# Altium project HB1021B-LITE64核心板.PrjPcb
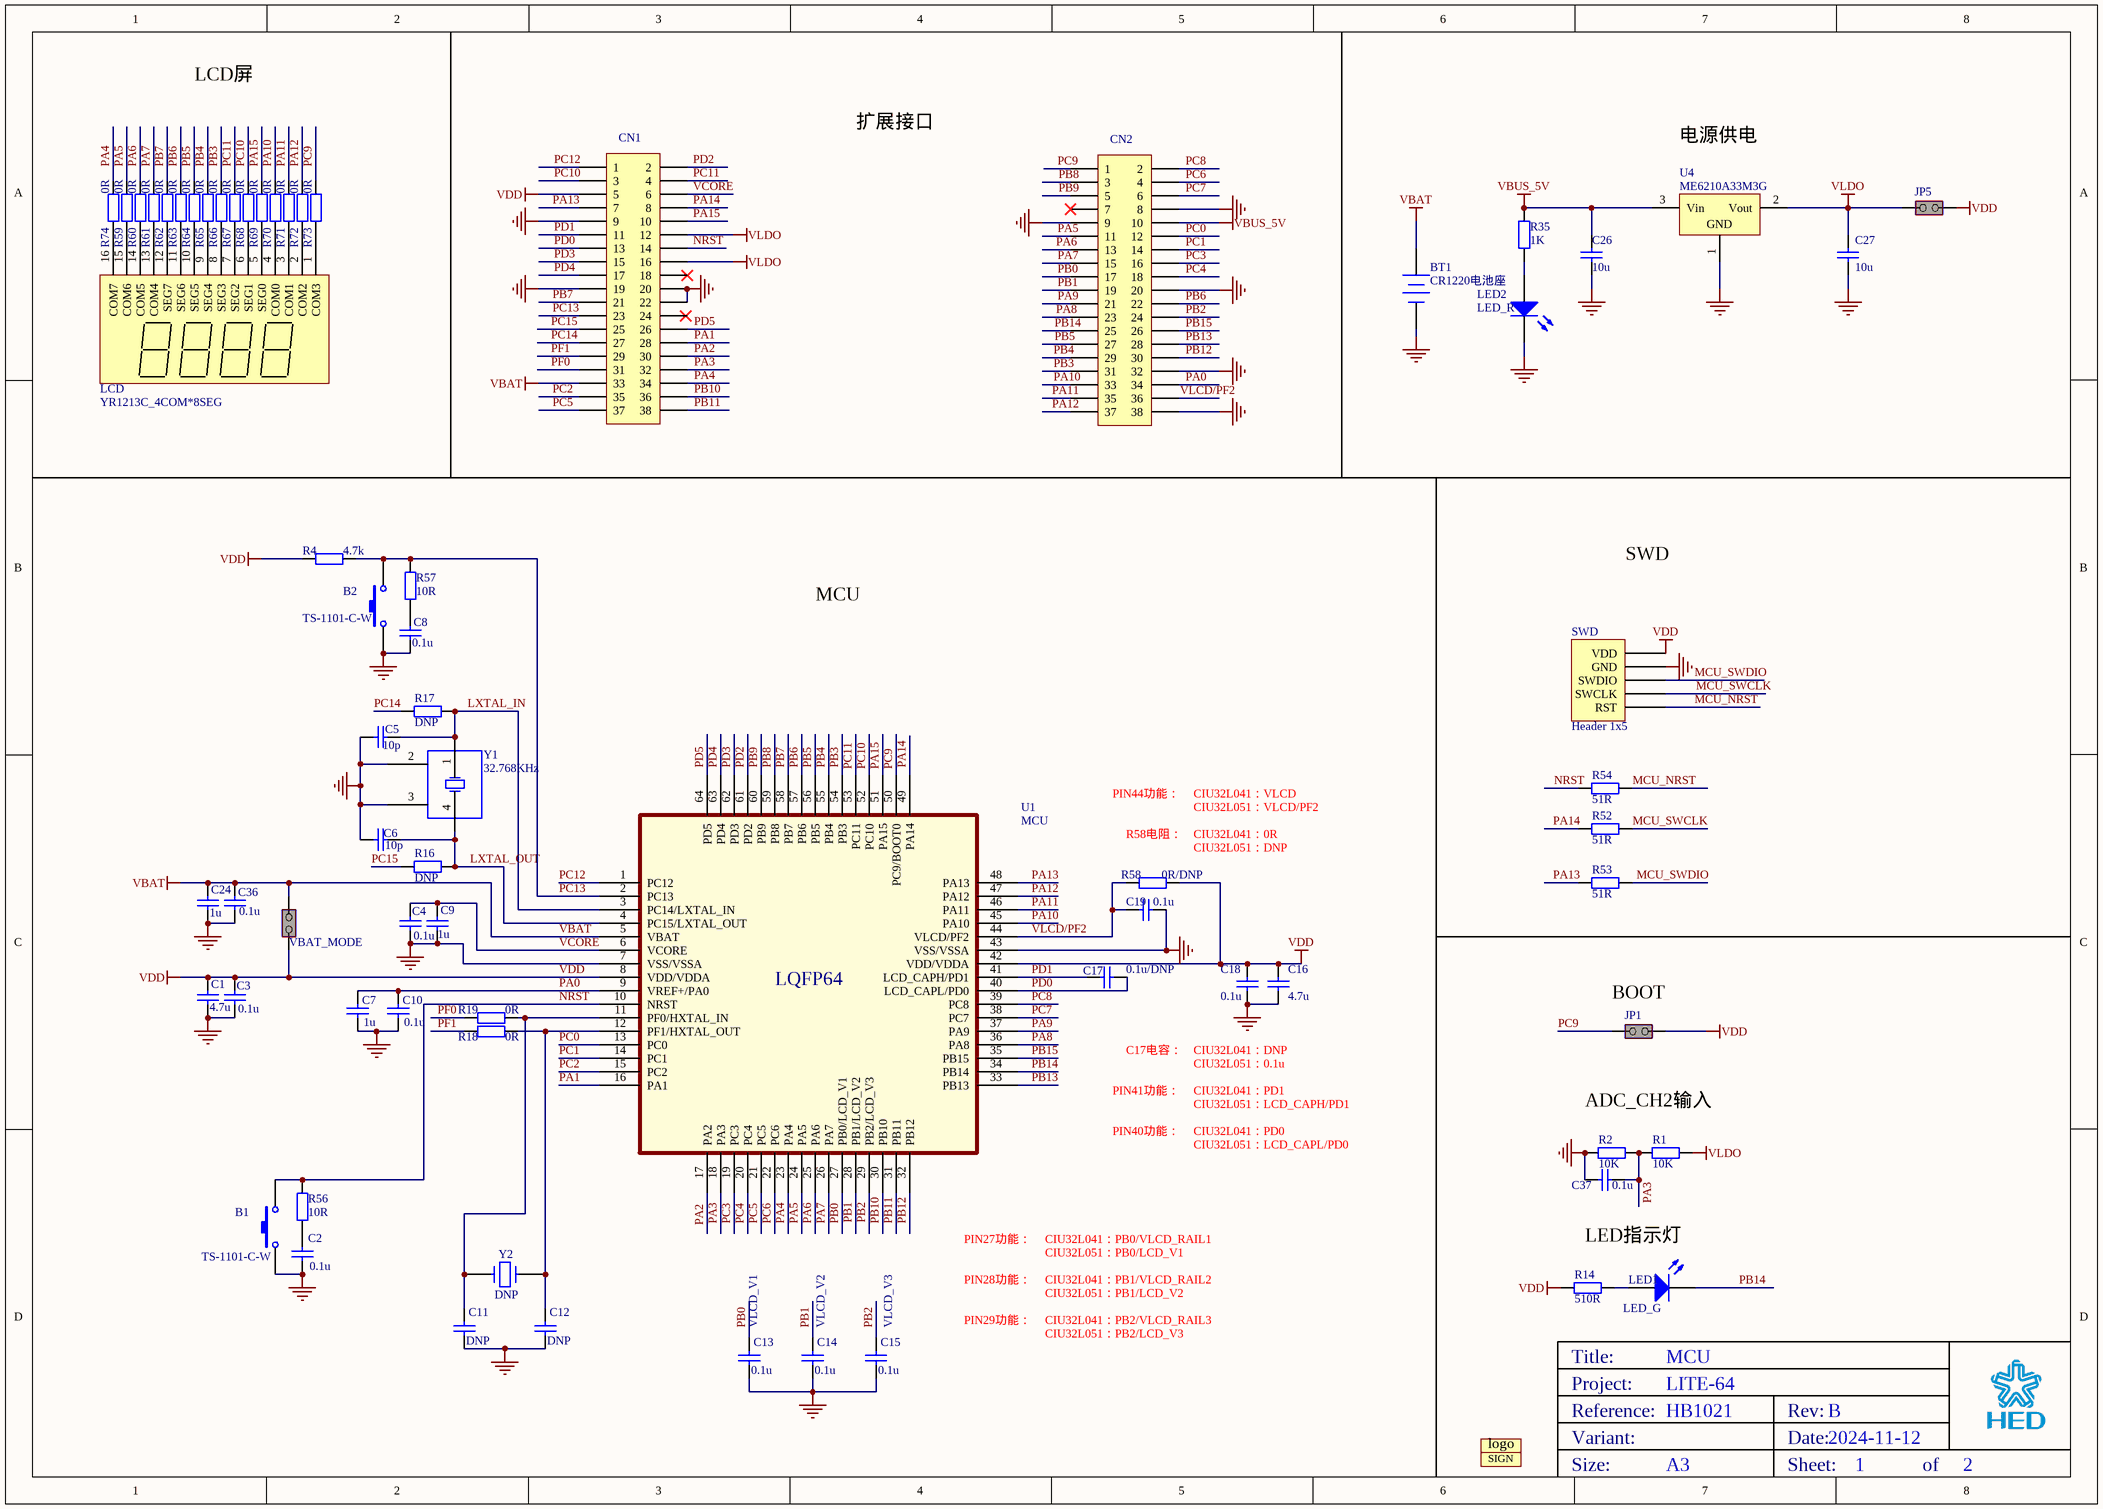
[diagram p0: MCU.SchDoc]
Board_Assembly_Revision: 01; Board_Name: LITE-64; Board_PCB_Revision: B; Board_Reference: HB1021
2 sheets, 113 parts. Net scope: global (net labels, ports and power ports of the same name join across sheets).
Board file: HB1021B.PcbDoc
Sheets:
  MCU.SchDoc
  LINK.SchDoc

## Sheet MCU.SchDoc: MCU
size A3; Date: 2024-11-12; DrawnBy: lidd; SheetNumber: 1; SheetTotal: 2

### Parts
B1  TS-1101-C-W  [按键_TS-1101-C-W]
B2  TS-1101-C-W  [按键_TS-1101-C-W]
BT1  CR1220电池座  [CR1220]
C1  4.7u  [0603]
C2  0.1u  [0603]
C3  0.1u  [0603]
C4  0.1u  [0603]
C5  10p  [0603]
C6  10p  [0603]
C7  1u  [0603]
C8  0.1u  [0603]
C9  1u  [0603]
C10  0.1u  [0603]
C11  DNP  [0603]
C12  DNP  [0603]
C13  0.1u  [0603]
C14  0.1u  [0603]
C15  0.1u  [0603]
C16  4.7u  [0603]
C17  0.1u/DNP  [0603]
C18  0.1u  [0603]
C19  0.1u  [0603]
C24  1u  [0603]
C26  10u  [0603]
C27  10u  [0603]
C36  0.1u  [0603]
C37  0.1u  [0603]
CN1  Header 19x2  [HEADER_1X19_2.54]  (value not drawn)
CN2  Header 19x2  [HEADER_1X19_2.54]  (value not drawn)
JP1  Header 1x2  [HEADER_1X2_2.54]  (value not drawn)
JP5  Header 1x2  [HEADER_1X2_2.54]  (value not drawn)
LCD  YR1213C_4COM*8SEG  [LCD_YR_8COM*8SEG]
LED1  LED_G  [0603 - p]
LED2  LED_R  [0603-P]
logo1  logo  [LOGO]  (value not drawn)
logo2  SIGN  [SIGN]  (value not drawn)
R1  10K  [0603]
R2  10K  [0603]
R4  4.7k  [0603]
R14  510R  [0603]
R16  DNP  [0603]
R17  DNP  [0603]
R18  0R  [0603]
R19  0R  [0603]
R35  1K  [0603]
R52  51R  [0603]
R53  51R  [0603]
R54  51R  [0603]
R56  10R  [0603]
R57  10R  [0603]
R58  0R/DNP  [0603]
R59  0R  [0603]
R60  0R  [0603]
R61  0R  [0603]
R62  0R  [0603]
R63  0R  [0603]
R64  0R  [0603]
R65  0R  [0603]
R66  0R  [0603]
R67  0R  [0603]
R68  0R  [0603]
R69  0R  [0603]
R70  0R  [0603]
R71  0R  [0603]
R72  0R  [0603]
R73  0R  [0603]
R74  0R  [0603]
SWD  Header 1x5  [HDR1X5_2.54]
U1  MCU  [LQFP_64N_7X7]
U4  ME6210A33M3G  [SOT-23-3]
VBAT_MODE  Header 1x2  [HEADER_1X2_2.54]  (value not drawn)
Y1  32.768KHz  [XTAL-MC146]
Y2  DNP  [XTAL_HC49/SMD]

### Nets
GND: B1.1 B2.1 BT1.2(-) C1.1 C2.2 C3.1 C4.2 C5.1 C6.1 C7.1 C8.1 C9.2 C10.1 C11.2 C12.2 C13.2 C14.2 C15.2 C16.2 C18.2 C19.1 C24.1 C26.1 C27.1 C36.1 C37.2 CN1.9 CN1.19 CN1.20 CN1.22 CN2.8 CN2.9 CN2.20 CN2.32 CN2.38 LED2.2(K) R2.1 SWD.2(GND) U1.7(VSS/VSSA) U1.43(VSS/VSSA) U4.1(GND) Y1.2(OSC2) Y1.3(OSC4)
VBAT: BT1.1(+) C24.2 C36.2 CN1.33 U1.5(VBAT) VBAT_MODE.2(NO)
VBUS_5V: C26.2 CN2.10 R35.2 U4.3(Vin)
VDD: C1.2 C3.2 C16.1 C18.1 CN1.5 JP1.2(NO) JP5.1(COMMON) R4.2 R14.2 R58.2 SWD.1(VDD) U1.8(VDD/VDDA) U1.42(VDD/VDDA) VBAT_MODE.1(COMMON)
VLDO: C27.2 CN1.12 CN1.16 JP5.2(NO) R1.2 U4.2(Vout)
LXTAL_IN: C5.2 R17.2 U1.3(PC14/LXTAL_IN) Y1.1(OSC1)
LXTAL_OUT: C6.2 R16.2 U1.4(PC15/LXTAL_OUT) Y1.4(OSC3)
MCU_NRST: R54.1 SWD.5(RST)  [project net LINK_RESET]
MCU_SWCLK: R52.1 SWD.4(SWCLK)
MCU_SWDIO: R53.1 SWD.3(SWDIO)
NRST: B1.2 CN1.14 R54.2 R56.1 U1.10(NRST)
PA0: C7.2 C10.2 CN2.34 U1.9(VREF+/PA0)
PA1: CN1.28 U1.16(PA1)
PA2: CN1.30 U1.17(PA2)
PA3: C37.1 CN1.32 R1.1 R2.2 U1.18(PA3)
PA4: CN1.34 R74.1 U1.23(PA4)
PA5: CN2.11 R59.1 U1.24(PA5)
PA6: CN2.13 R60.1 U1.25(PA6)
PA7: CN2.15 R61.1 U1.26(PA7)
PA8: CN2.23 U1.36(PA8)
PA9: CN2.21 U1.37(PA9)
PA10: CN2.33 R70.1 U1.45(PA10)
PA11: CN2.35 R71.1 U1.46(PA11)
PA12: CN2.37 R72.1 U1.47(PA12)
PA13: CN1.7 R53.2 U1.48(PA13)
PA14: CN1.8 R52.2 U1.49(PA14)
PA15: CN1.10 R69.1 U1.51(PA15)
PB0: C13.1 CN2.17 U1.27(PB0/LCD_V1)
PB1: C14.1 CN2.19 U1.28(PB1/LCD_V2)
PB2: C15.1 CN2.24 U1.29(PB2/LCD_V3)
PB3: CN2.31 R66.1 U1.54(PB3)
PB4: CN2.29 R65.1 U1.55(PB4)
PB5: CN2.27 R64.1 U1.56(PB5)
PB6: CN2.22 R63.1 U1.57(PB6)
PB7: CN1.21 R62.1 U1.58(PB7)
PB8: CN2.3 U1.59(PB8)
PB9: CN2.5 U1.60(PB9)
PB10: CN1.36 U1.30(PB10)
PB11: CN1.38 U1.31(PB11)
PB12: CN2.30 U1.32(PB12)
PB13: CN2.28 U1.33(PB13)
PB14: CN2.25 LED1.2(K) U1.34(PB14)
PB15: CN2.26 U1.35(PB15)
PC0: CN2.12 U1.13(PC0)
PC1: CN2.14 U1.14(PC1)
PC2: CN1.35 U1.15(PC2)
PC3: CN2.16 U1.19(PC3)
PC4: CN2.18 U1.20(PC4)
PC5: CN1.37 U1.21(PC5)
PC6: CN2.4 U1.22(PC6)
PC7: CN2.6 U1.38(PC7)
PC8: CN2.2 U1.39(PC8)
PC9: CN2.1 JP1.1(COMMON) R73.1 U1.50(PC9/BOOT0)
PC10: CN1.3 R68.1 U1.52(PC10)
PC11: CN1.4 R67.1 U1.53(PC11)
PC12: CN1.1 U1.1(PC12)
PC13: B2.2 CN1.23 R4.1 R57.1 U1.2(PC13)
PC14: CN1.27 R17.1
PC15: CN1.25 R16.1
PD0: C17.1 CN1.13 U1.40(LCD_CAPL/PD0)
PD1: C17.2 CN1.11 U1.41(LCD_CAPH/PD1)
PD2: CN1.2 U1.61(PD2)
PD3: CN1.15 U1.62(PD3)
PD4: CN1.17 U1.63(PD4)
PD5: CN1.26 U1.64(PD5)
PF0: CN1.31 R19.2
PF1: CN1.29 R18.2
VCORE: C4.1 C9.1 CN1.6 U1.6(VCORE)
VLCD/PF2: C19.2 CN2.36 R58.1 U1.44(VLCD/PF2)
NetC2_1: C2.1 R56.2
NetC8_2: C8.2 R57.2
NetC11_1: C11.1 R19.1 U1.11(PF0/HXTAL_IN) Y2.1
NetC12_1: C12.1 R18.1 U1.12(PF1/HXTAL_OUT) Y2.2
NetLCD_1: LCD.1(COM3) R73.2
NetLCD_2: LCD.2(COM2) R72.2
NetLCD_3: LCD.3(COM1) R71.2
NetLCD_4: LCD.4(COM0) R70.2
NetLCD_5: LCD.5(SEG0) R69.2
NetLCD_6: LCD.6(SEG1) R68.2
NetLCD_7: LCD.7(SEG2) R67.2
NetLCD_8: LCD.8(SEG3) R66.2
NetLCD_9: LCD.9(SEG4) R65.2
NetLCD_10: LCD.10(SEG5) R64.2
NetLCD_11: LCD.11(SEG6) R63.2
NetLCD_12: LCD.12(SEG7) R62.2
NetLCD_13: LCD.13(COM4) R61.2
NetLCD_14: LCD.14(COM5) R60.2
NetLCD_15: LCD.15(COM6) R59.2
NetLCD_16: LCD.16(COM7) R74.2
NetLED1_1: LED1.1(A) R14.1
NetLED2_1: LED2.1(A) R35.1

Not connected (* = marked no-connect by the designer): CN1 18* 24; CN2 7*

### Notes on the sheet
- LCD屏
- 扩展接口
- 电源供电
- SWD
- MCU
- PIN44功能：
- (near R58) R58电阻：
- (near R58) CIU32L041：0R
- (near R58) CIU32L051：DNP
- CIU32L041：VLCD
- CIU32L051：VLCD/PF2
- C17电容：
- CIU32L041：DNP
- (near JP1) BOOT
- PIN41功能：
- CIU32L041：PD1
- CIU32L051：LCD_CAPH/PD1
- CIU32L051：0.1u
- ADC_CH2输入
- PIN40功能：
- CIU32L041：PD0
- CIU32L051：LCD_CAPL/PD0
- PIN27功能：
- CIU32L041：PB0/VLCD_RAIL1
- CIU32L051：PB0/LCD_V1
- LED指示灯
- (near C13) VLCD_V1
- (near C14) VLCD_V2
- (near C15) VLCD_V3
- PIN28功能：
- PIN29功能：
- CIU32L041：PB1/VLCD_RAIL2
- CIU32L051：PB1/LCD_V2
- CIU32L041：PB2/VLCD_RAIL3
- CIU32L051：PB2/LCD_V3

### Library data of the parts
B1 B2 = SW-PB: 贴片按键
BT1 = Battery: 贴片CR1220电池座
C1 C13-C16 C19 C24 C36 C37 = MCD-00009: Capacitor, MLCC, 4.7uF, 16V, X5R, 10%, 0603, T=0.8mm; Manufacturer_Part_Number: CC0603KRX5R7BB475; Manufacturer: YAGEO; Provided_By: subcon; Initial_Board_Reference: mb1274
C2-C4 C7 C9 C10 C18 = MCD-00211: Capacitor, MLCC, 100nF, 16V, X7R, 10%, 0603, T=0,8mm; Manufacturer_Part_Number: CC0603KRX7R7BB104; Manufacturer: YAGEO; Provided_By: Subcon; Initial_Board_Reference: mb1319
C5 C6 = MCD-00666: Capacitor,5.6pF,0.1pF,16V,NPO,0603; Manufacturer_Part_Number: CC0603BRNPO7BN5R6; Manufacturer: YAGEO; Provided_By: Subcon; Initial_Board_Reference: MB1360
C8 = MCD-00211: 贴片电容; Manufacturer_Part_Number: CC0603KRX7R7BB104; Manufacturer: YAGEO; Provided_By: Subcon; Initial_Board_Reference: mb1319
C11 C12 = MCD-00009: 贴片电容33p; Manufacturer_Part_Number: CC0603KRX5R7BB475; Manufacturer: YAGEO; Provided_By: subcon; Initial_Board_Reference: mb1274
C17 = MCD-00009: Capacitor, MLCC, 4.7uF, 16V, X5R, 10%, 0603, T=0.8mm; Manufacturer_Part_Number: CC0603KRX5R7BB475; Manufacturer: YAGEO; Value: 0.1u; Provided_By: subcon; Initial_Board_Reference: mb1274
C26 C27 = MCD-00014: Capacitor, MLCC, 10uF, 25V, X5R, 10%, 0805, T=0,85mm; Manufacturer_Part_Number: CC0805KRX5R8BB106; Manufacturer: YAGEO; Provided_By: Subcon; Initial_Board_Reference: mb1274
CN1 CN2 = Header 19x2: Header, 19x2, 2,54mm, VR, TH, Height 5.84mm/10.16mm; Internal_Part_Number: MCD-00213; Manufacturer: SAMTEC; Part_Type: Connector; Manufacturer_Part_Number: TSW-119-09-x-D1; Provided_By: Subcon; Initial_Board_Reference: mb1319
JP1 JP5 VBAT_MODE = MCD-00683: Header, 2x1, 2,54mm, VR, TH, Height 5.84mm/2.54mm - Shunt Fitted by default; Part_Type: Connector; Manufacturer_Part_Number: TSW-102-07-x-S; Manufacturer: SAMTEC; Provided_By: Subcon; Initial_Board_Reference: MB1331
LCD = LCD8COM*8SEG: Common Anode Seven-Segment Display, Right Hand Decimal; Manufacturer: 苏州扬润电子
LED1 = LED1: 贴片LED 绿色
LED2 = LED1: 贴片LED 红色
R1 R2 R35 R59-R74 = Res2: 贴片电阻
R4 R14 R16-R19 R56 R57 = Res2: 贴片电阻; Value: 1K
R52-R54 = Res: 贴片电阻
R58 = Res2: 贴片电阻; Value: 0R
SWD = SWD: Header, 1x5, 2,54mm, VR, TH, Height 5.84mm/2.54mm
U1 = CIU32L071Rx-LQFP64: CIU32L0x1
U4 = ME6210: 贴片LDO3.3V; Manufacturer: 微盟电子
Y1 = MC146: 贴片晶振
Y2 = XTAL_32K_NX3215SA: Crystal 32.768kHz, 6pF, -+20PPM, R=50K, SMD; Internal_Part_Number: MCD-00091; Part_Type: Crystal_Osc; Manufacturer_Part_Number: NX3215SA 32.768KHz EXS00A-MU00525; Manufacturer: NDK; ECCN_US: EAR99; ECCN_EU: NEC; Provided_By: STM; Initial_Board_Reference: mb1274

## Sheet LINK.SchDoc: LINK
size A4; Date: 2024-11-12; DrawnBy: Lidd; SheetNumber: 2; SheetTotal: 2
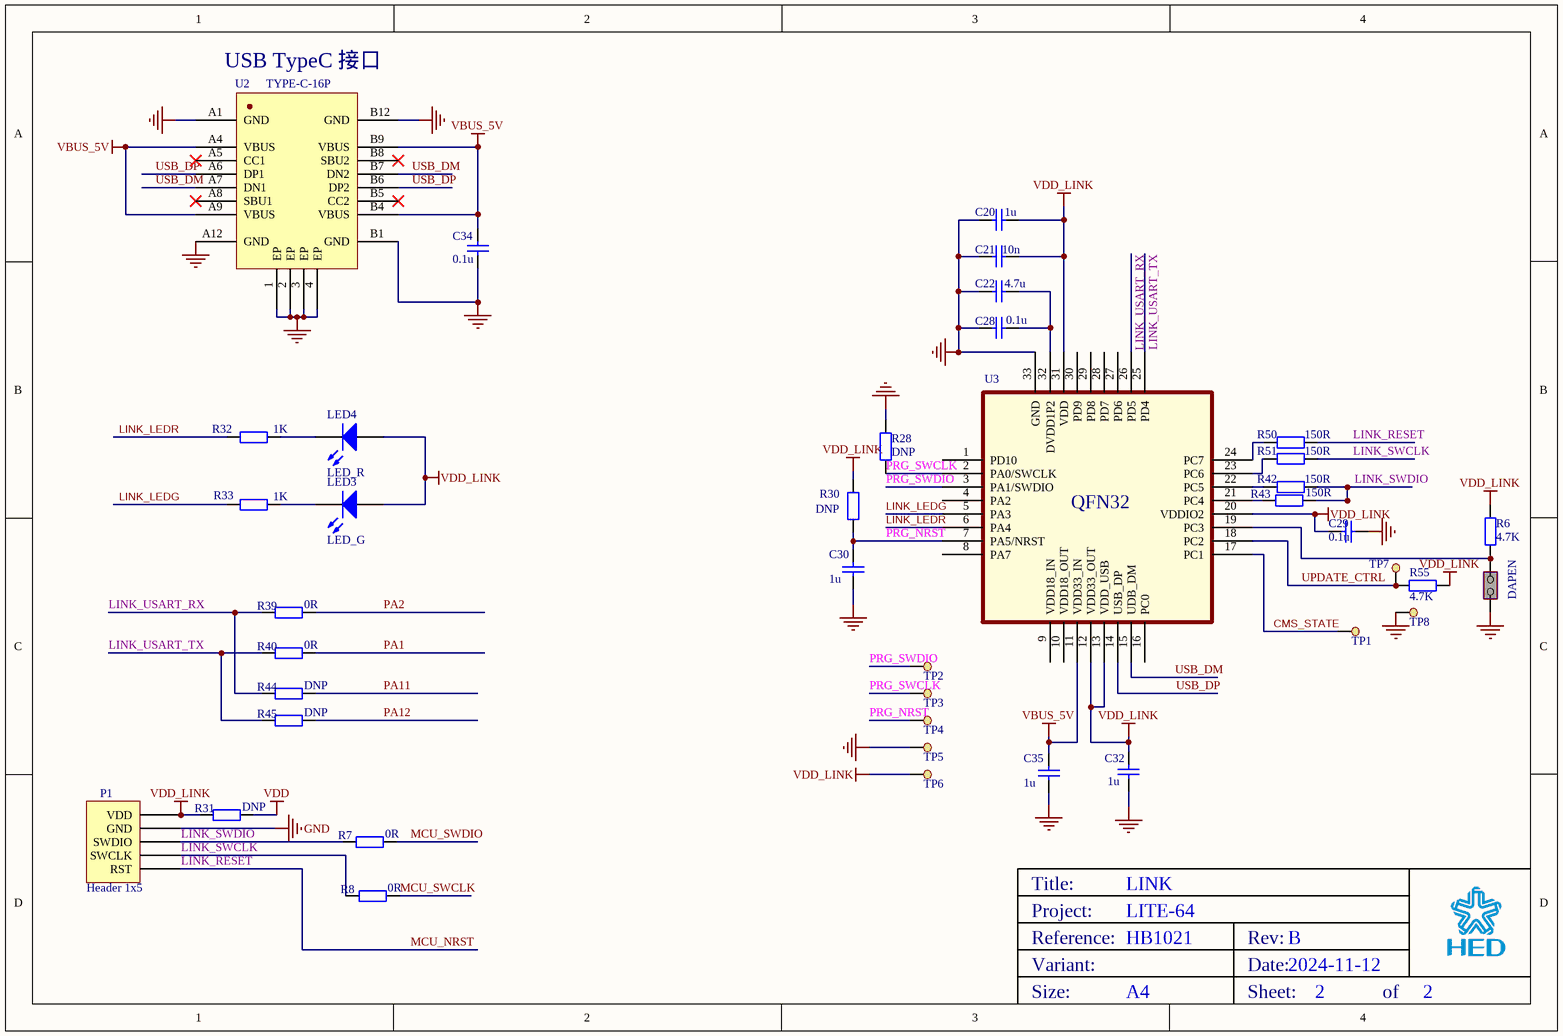
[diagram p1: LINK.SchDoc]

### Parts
C20  1u  [0603]
C21  10n  [0603]
C22  4.7u  [0603]
C28  0.1u  [0603]
C29  0.1u  [0603]
C30  value 1u  [0603]  (hidden comment: 0.1u)
C32  1u  [0603]
C34  0.1u  [0603]
C35  1u  [0603]
DAPEN  Header 1x2  [HEADER_1X2_2.54]  (value not drawn)
LED3  LED_G  [0603-P]
LED4  LED_R  [0603-P]
P1  Header 1x5  [HDR1X5_2.54]
R6  4.7K  [0603]
R7  0R  [0603]
R8  0R  [0603]
R28  DNP  [0603]
R30  DNP  [0603]
R31  DNP  [0603]
R32  1K  [0603]
R33  1K  [0603]
R39  0R  [0603]
R40  0R  [0603]
R42  150R  [0603]
R43  150R  [0603]
R44  DNP  [0603]
R45  DNP  [0603]
R50  150R  [0603]
R51  150R  [0603]
R55  4.7K  [0603]
TP1  TEST_POINT  [TEST_POINT]  (value not drawn)
TP2  TEST_POINT  [TEST_POINT]  (value not drawn)
TP3  TEST_POINT  [TEST_POINT]  (value not drawn)
TP4  TEST_POINT  [TEST_POINT]  (value not drawn)
TP5  TEST_POINT  [TEST_POINT]  (value not drawn)
TP6  TEST_POINT  [TEST_POINT]  (value not drawn)
TP7  TEST_POINT  [TEST_POINT]  (value not drawn)
TP8  TEST_POINT  [TEST_POINT]  (value not drawn)
U2  TYPE-C-16P  [HED-KH-TYPE-C-16P]
U3  CIU98_H  [HED-QFN-32_5x5x05P]  (value not drawn)

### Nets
GND: C20.1 C21.1 C22.1 C28.1 C29.1 C30.2 C32.2 C34.1 C35.2 DAPEN.2(NO) P1.2(GND) R28.1 TP5.1 TP8.1 U2.1(EP) U2.2(EP) U2.3(EP) U2.4(EP) U2.A1(GND) U2.A12(GND) U2.B1(GND) U2.B12(GND) U3.33(GND)
VBUS_5V: C34.2 C35.1 U2.A4(VBUS) U2.A9(VBUS) U2.B4(VBUS) U2.B9(VBUS) U3.11(VDD33_IN)
VDD: R31.2
VDD_LINK: C20.2 C21.2 C29.2 C32.1 LED3.1(A) LED4.1(A) P1.1(VDD) R6.2 R30.1 R31.1 R55.1 TP6.1 U3.12(VDD33_OUT) U3.13(VDD_USB) U3.20(VDDIO2) U3.31(VDD)
CMS_STATE: TP1.1 U3.17(PC1)
LINK_LEDG: R33.1 U3.5(PA3)
LINK_LEDR: R32.1 U3.6(PA4)
LINK_RESET: P1.5(RST) R50.2  [also labelled MCU_NRST]
LINK_SWCLK: P1.4(SWCLK) R8.1 R51.2
LINK_SWDIO: P1.3(SWDIO) R7.1 R42.2 R43.2
LINK_USART_RX: R39.1 R44.1 U3.26(PD5)
LINK_USART_TX: R40.1 R45.1 U3.25(PD4)
MCU_SWCLK: R8.2
MCU_SWDIO: R7.2
PA1: R40.2
PA2: R39.2
PA11: R44.2
PA12: R45.2
PRG_NRST: C30.1 R30.2 TP4.1 U3.7(PA5/NRST)
PRG_SWCLK: R28.2 TP3.1 U3.2(PA0/SWCLK)
PRG_SWDIO: TP2.1 U3.3(PA1/SWDIO)
UPDATE_CTRL: R55.2 TP7.1 U3.18(PC2)
USB_DM: U2.A7(DN1) U2.B7(DN2) U3.15(UDB_DM)
USB_DP: U2.A6(DP1) U2.B6(DP2) U3.14(USB_DP)
NetC22_2: C22.2 C28.2 U3.32(DVDD1P2)
NetDAPEN_1: DAPEN.1(COMMON) R6.1 U3.19(PC3)
NetLED3_2: LED3.2(K) R33.2
NetLED4_2: LED4.2(K) R32.2
NetR42_1: R42.1 U3.22(PC5)
NetR43_1: R43.1 U3.21(PC4)
NetR50_1: R50.1 U3.24(PC7)
NetR51_1: R51.1 U3.23(PC6)

Not connected (* = marked no-connect by the designer): U2 A5(CC1)* A8(SBU1)* B5(CC2)* B8(SBU2)*; U3 1(PD10) 4(PA2) 8(PA7) 9(VDD18_IN) 10(VDD18_OUT) 16(PC0) 27(PD6) 28(PD7) 29(PD8) 30(PD9)

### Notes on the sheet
- (near U2) USB TypeC 接口

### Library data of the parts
C20-C22 C28-C30 C32 C35 = MCD-00211: as C2 on sheet MCU
C34 = 0603 100nF 10% 50V: 贴片电容
DAPEN = MCD-00683: as JP1 on sheet MCU
LED3 = LED1: 贴片LED 绿色
LED4 = LED1: 贴片LED 红色
P1 = SWD: as SWD on sheet MCU
R6 R55 = Res: 贴片电阻
R7 R8 R32 R33 R39 R40 R44 R45 = Res2: 贴片电阻
R28 R42 R43 R50 R51 = Res: 贴片电阻; Value: 1K
R30 R31 = Res2: 贴片电阻; Value: 1K
U2 = KH-TYPE-C-16P: TYPE-C USB接口
U3 = CIU98-H: 贴片芯片

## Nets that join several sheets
GND: MCU (43 pins), LINK (23 pins)
VBUS_5V: MCU (C26.2 CN2.10 R35.2 U4.3), LINK (7 pins)
VDD: MCU (14 pins), LINK (R31.2)
LINK_RESET: MCU (R54.1 SWD.5), LINK (P1.5 R50.2)
MCU_SWCLK: MCU (R52.1 SWD.4), LINK (R8.2)
MCU_SWDIO: MCU (R53.1 SWD.3), LINK (R7.2)
PA1: MCU (CN1.28 U1.16), LINK (R40.2)
PA2: MCU (CN1.30 U1.17), LINK (R39.2)
PA11: MCU (CN2.35 R71.1 U1.46), LINK (R44.2)
PA12: MCU (CN2.37 R72.1 U1.47), LINK (R45.2)

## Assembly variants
Default: all parts fitted
HB1021B-CIU32L051-LITE64_BOM: not fitted C11 C12 logo1 logo2 R16 R17 R28 R30 R31 R44 R45 R58 TP1 TP2 TP3 TP4 TP5 TP6 TP7 TP8 Y2
HB1021B-CIU32L041-LITE64_BOM: not fitted C11 C12 C17 logo1 logo2 R16 R17 R28 R30 R31 R44 R45 TP1 TP2 TP3 TP4 TP5 TP6 TP7 TP8 Y2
